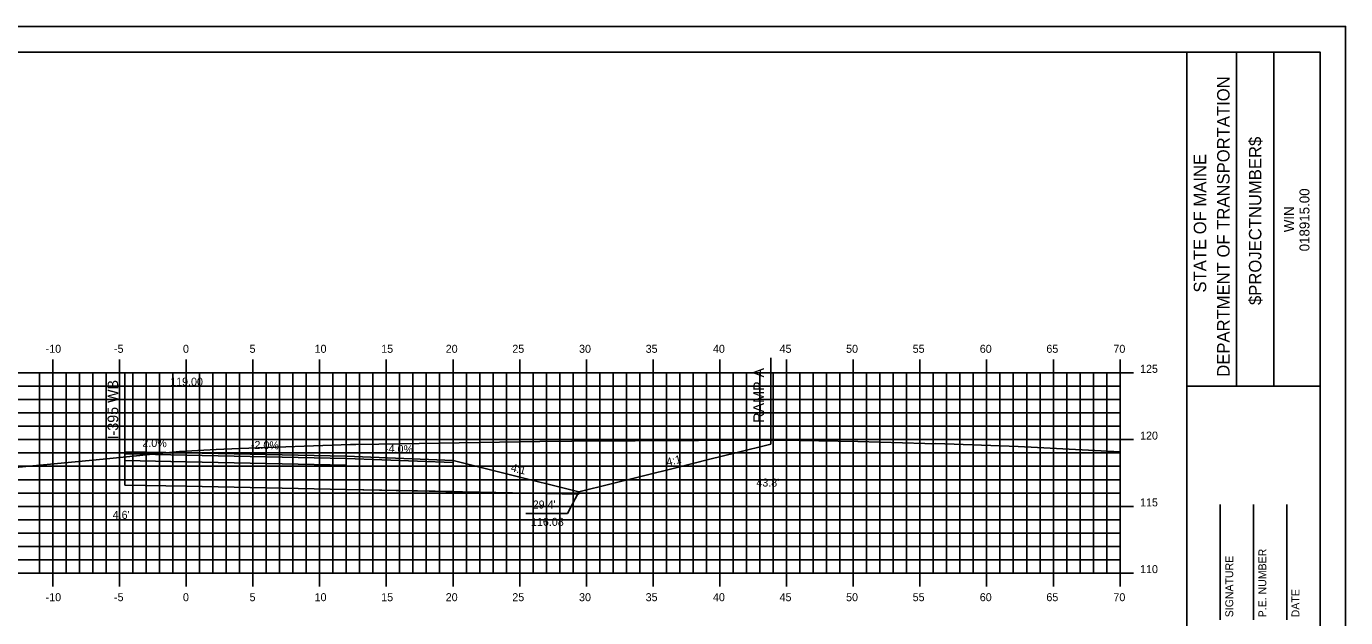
# Model space of a CAD drawing. Extents: x 853291 to 853462, y 365624 to 365734.
# Drawn here: x 853361.8 to 853460.7, y 365689.7 to 365734 of the extents above; entities that cross this region are included whole.
import ezdxf

# ---------------------------------------------------------------- set-up
doc = ezdxf.new("R2010")
doc.units = 0
for name, color, linetype in [('ANNOTATION', 7, 'Continuous'), ('BORDER', 7, 'Continuous'), ('D_Roadway_Centerline', 7, 'Continuous'), ('D_Roadway_Centerline_Text', 7, 'Continuous'), ('D_Roadway_Edge_Shoulder', 7, 'Continuous'), ('D_Roadway_Edge_TW', 7, 'Continuous'), ('D_Roadway_FinishedGrade', 7, 'Continuous'), ('D_Roadway_Pavement', 7, 'Continuous'), ('D_Roadway_SubGrade', 7, 'Continuous'), ('D_Text_Standard', 7, 'Continuous'), ('Default', 7, 'Continuous'), ('H_V ANNOTATION', 7, 'Continuous'), ('M_Roadway_Centerline', 7, 'Continuous'), ('MAJOR', 7, 'Continuous'), ('MINOR', 7, 'Continuous'), ('PLOT BOUNDARY', 7, 'Continuous'), ('S_Roadway_Centerline', 7, 'Continuous')]:
    doc.layers.add(name, color=color, linetype=linetype)

msp = doc.modelspace()

# ---------------------------------------------------------------- linework, layer by layer
at = {"layer": 'ANNOTATION'}
msp.add_lwpolyline([(853399.279, 365697.505), (853402.389, 365697.505), (853403.254, 365699.11)], dxfattribs=at)
at = {"layer": 'BORDER'}
for p, q in [((853448.818, 365627.027), (853448.818, 365732.027)), ((853452.547, 365707.024), (853452.547, 365732.024)), ((853455.342, 365707.024), (853455.342, 365732.024)), ((853448.819, 365707.021), (853458.818, 365707.021)), ((853451.318, 365689.53), (853451.318, 365698.177)), ((853453.818, 365689.53), (853453.818, 365698.177)), ((853456.318, 365689.53), (853456.318, 365698.177))]:
    msp.add_line(p, q, dxfattribs=at)
msp.add_lwpolyline([(853298.818, 365627.027), (853458.818, 365627.027), (853458.818, 365732.027), (853298.818, 365732.027)], close=True, dxfattribs=at)
at = {"layer": 'D_Roadway_Centerline'}
msp.add_line((853393.818, 365699.129), (853393.818, 365699.129), dxfattribs=at)
for points in [[(853403.254, 365699.11), (853410.521, 365700.918), (853413.07, 365701.552), (853415.017, 365702.036), (853417.64, 365702.689)], [(853369.231, 365702.121), (853369.232, 365702.121), (853373.818, 365702.029), (853373.819, 365702.029), (853385.818, 365701.789), (853393.818, 365701.469)], [(853393.818, 365701.469), (853397.818, 365700.469), (853403.254, 365699.11)]]:
    msp.add_lwpolyline(points, dxfattribs=at)
at = {"layer": 'D_Roadway_Edge_Shoulder'}
for points in [[(853373.818, 365702.029), (853369.231, 365702.121), (853369.231, 365701.954), (853373.818, 365701.862)], [(853385.818, 365701.789), (853393.818, 365701.469), (853393.818, 365701.302), (853385.818, 365701.622)]]:
    msp.add_lwpolyline(points, close=True, dxfattribs=at)
at = {"layer": 'D_Roadway_Edge_TW'}
msp.add_lwpolyline([(853373.818, 365702.029), (853385.818, 365701.789), (853385.818, 365701.622), (853373.818, 365701.862)], close=True, dxfattribs=at)
msp.add_lwpolyline([(853385.818, 365701.789), (853385.818, 365701.622)], dxfattribs=at)
at = {"layer": 'D_Roadway_FinishedGrade'}
for p, q in [((853369.231, 365702.121), (853369.231, 365701.871)), ((853369.231, 365702.037), (853369.231, 365701.787)), ((853373.818, 365702.029), (853373.818, 365701.779)), ((853385.818, 365701.789), (853385.818, 365701.539)), ((853393.818, 365701.469), (853393.818, 365701.219))]:
    msp.add_line(p, q, dxfattribs=at)
at = {"layer": 'D_Roadway_Pavement'}
for points in [[(853373.818, 365701.862), (853369.231, 365701.954), (853369.231, 365701.454), (853373.818, 365701.362)], [(853373.818, 365701.862), (853385.818, 365701.622), (853385.818, 365701.122), (853373.818, 365701.362)]]:
    msp.add_lwpolyline(points, close=True, dxfattribs=at)
msp.add_lwpolyline([(853385.818, 365701.622), (853385.818, 365701.122)], dxfattribs=at)
msp.add_lwpolyline([(853385.818, 365701.622), (853385.818, 365701.122)], dxfattribs=at)
at = {"layer": 'D_Roadway_SubGrade'}
for p, q in [((853417.64, 365709.151), (853417.64, 365702.689)), ((853369.231, 365708.025), (853369.231, 365699.621)), ((853385.818, 365699.289), (853403.254, 365698.94)), ((853403.254, 365699.11), (853403.254, 365698.94))]:
    msp.add_line(p, q, dxfattribs=at)
for points in [[(853373.818, 365701.362), (853369.231, 365701.454), (853369.231, 365701.954), (853369.231, 365702.121), (853369.231, 365699.621), (853373.818, 365699.529)], [(853385.818, 365701.122), (853385.818, 365701.622), (853393.818, 365701.302), (853393.818, 365701.469), (853393.818, 365699.129), (853385.818, 365699.289)], [(853373.818, 365701.362), (853385.818, 365701.122), (853385.818, 365699.289), (853373.818, 365699.529)]]:
    msp.add_lwpolyline(points, close=True, dxfattribs=at)
msp.add_lwpolyline([(853385.818, 365701.122), (853385.818, 365699.289)], dxfattribs=at)
at = {"layer": 'Default'}
msp.add_lwpolyline([(853393.818, 365701.469), (853397.818, 365700.469), (853403.254, 365699.11)], dxfattribs=at)
at = {"layer": 'MAJOR'}
for p, q in [((853363.818, 365709.029), (853363.818, 365708.027)), ((853368.818, 365709.029), (853368.818, 365708.027)), ((853373.818, 365709.029), (853373.818, 365708.027)), ((853378.818, 365709.029), (853378.818, 365708.027)), ((853383.818, 365709.029), (853383.818, 365708.027)), ((853388.818, 365709.029), (853388.818, 365708.027)), ((853393.818, 365709.029), (853393.818, 365708.027)), ((853398.818, 365709.029), (853398.818, 365708.027)), ((853403.818, 365709.029), (853403.818, 365708.027)), ((853408.818, 365709.029), (853408.818, 365708.027)), ((853413.818, 365709.029), (853413.818, 365708.027)), ((853418.818, 365709.029), (853418.818, 365708.027)), ((853423.818, 365709.029), (853423.818, 365708.027)), ((853428.818, 365709.029), (853428.818, 365708.027)), ((853433.818, 365709.029), (853433.818, 365708.027)), ((853438.818, 365709.029), (853438.818, 365708.027)), ((853443.818, 365709.029), (853443.818, 365708.027)), ((853303.818, 365708.027), (853443.818, 365708.027)), ((853303.818, 365708.027), (853443.818, 365708.027)), ((853363.818, 365693.027), (853363.818, 365708.027)), ((853368.818, 365693.027), (853368.818, 365708.027)), ((853373.818, 365693.027), (853373.818, 365708.027)), ((853378.818, 365693.027), (853378.818, 365708.027)), ((853383.818, 365693.027), (853383.818, 365708.027)), ((853388.818, 365693.027), (853388.818, 365708.027)), ((853393.818, 365693.027), (853393.818, 365708.027)), ((853398.818, 365693.027), (853398.818, 365708.027)), ((853403.818, 365693.027), (853403.818, 365708.027)), ((853408.818, 365693.027), (853408.818, 365708.027)), ((853413.818, 365693.027), (853413.818, 365708.027)), ((853418.818, 365693.027), (853418.818, 365708.027)), ((853423.818, 365693.027), (853423.818, 365708.027)), ((853428.818, 365693.027), (853428.818, 365708.027)), ((853433.818, 365693.027), (853433.818, 365708.027)), ((853438.818, 365693.027), (853438.818, 365708.027)), ((853444.82, 365708.027), (853442.816, 365708.027)), ((853443.818, 365693.027), (853443.818, 365708.027)), ((853443.818, 365693.027), (853443.818, 365708.027)), ((853303.818, 365703.027), (853443.818, 365703.027)), ((853444.82, 365703.027), (853442.816, 365703.027)), ((853303.818, 365698.027), (853443.818, 365698.027)), ((853444.82, 365698.027), (853442.816, 365698.027)), ((853303.818, 365693.027), (853443.818, 365693.027)), ((853303.818, 365693.027), (853443.818, 365693.027)), ((853363.818, 365692.025), (853363.818, 365693.027)), ((853368.818, 365692.025), (853368.818, 365693.027)), ((853373.818, 365692.025), (853373.818, 365693.027)), ((853378.818, 365692.025), (853378.818, 365693.027)), ((853383.818, 365692.025), (853383.818, 365693.027)), ((853388.818, 365692.025), (853388.818, 365693.027)), ((853393.818, 365692.025), (853393.818, 365693.027)), ((853398.818, 365692.025), (853398.818, 365693.027)), ((853403.818, 365692.025), (853403.818, 365693.027)), ((853408.818, 365692.025), (853408.818, 365693.027)), ((853413.818, 365692.025), (853413.818, 365693.027)), ((853418.818, 365692.025), (853418.818, 365693.027)), ((853423.818, 365692.025), (853423.818, 365693.027)), ((853428.818, 365692.025), (853428.818, 365693.027)), ((853433.818, 365692.025), (853433.818, 365693.027)), ((853438.818, 365692.025), (853438.818, 365693.027)), ((853444.82, 365693.027), (853442.816, 365693.027)), ((853443.818, 365692.025), (853443.818, 365693.027))]:
    msp.add_line(p, q, dxfattribs=at)
at = {"layer": 'MINOR'}
for p, q in [((853362.818, 365693.027), (853362.818, 365708.027)), ((853364.818, 365693.027), (853364.818, 365708.027)), ((853365.818, 365693.027), (853365.818, 365708.027)), ((853366.818, 365693.027), (853366.818, 365708.027)), ((853367.818, 365693.027), (853367.818, 365708.027)), ((853369.818, 365693.027), (853369.818, 365708.027)), ((853370.818, 365693.027), (853370.818, 365708.027)), ((853371.818, 365693.027), (853371.818, 365708.027)), ((853372.818, 365693.027), (853372.818, 365708.027)), ((853374.818, 365693.027), (853374.818, 365708.027)), ((853375.818, 365693.027), (853375.818, 365708.027)), ((853376.818, 365693.027), (853376.818, 365708.027)), ((853377.818, 365693.027), (853377.818, 365708.027)), ((853379.818, 365693.027), (853379.818, 365708.027)), ((853380.818, 365693.027), (853380.818, 365708.027)), ((853381.818, 365693.027), (853381.818, 365708.027)), ((853382.818, 365693.027), (853382.818, 365708.027)), ((853384.818, 365693.027), (853384.818, 365708.027)), ((853385.818, 365693.027), (853385.818, 365708.027)), ((853386.818, 365693.027), (853386.818, 365708.027)), ((853387.818, 365693.027), (853387.818, 365708.027)), ((853389.818, 365693.027), (853389.818, 365708.027)), ((853390.818, 365693.027), (853390.818, 365708.027)), ((853391.818, 365693.027), (853391.818, 365708.027)), ((853392.818, 365693.027), (853392.818, 365708.027)), ((853394.818, 365693.027), (853394.818, 365708.027)), ((853395.818, 365693.027), (853395.818, 365708.027)), ((853396.818, 365693.027), (853396.818, 365708.027)), ((853397.818, 365693.027), (853397.818, 365708.027)), ((853399.818, 365693.027), (853399.818, 365708.027)), ((853400.818, 365693.027), (853400.818, 365708.027)), ((853401.818, 365693.027), (853401.818, 365708.027)), ((853402.818, 365693.027), (853402.818, 365708.027)), ((853404.818, 365693.027), (853404.818, 365708.027)), ((853405.818, 365693.027), (853405.818, 365708.027)), ((853406.818, 365693.027), (853406.818, 365708.027)), ((853407.818, 365693.027), (853407.818, 365708.027)), ((853409.818, 365693.027), (853409.818, 365708.027)), ((853410.818, 365693.027), (853410.818, 365708.027)), ((853411.818, 365693.027), (853411.818, 365708.027)), ((853412.818, 365693.027), (853412.818, 365708.027)), ((853414.818, 365693.027), (853414.818, 365708.027)), ((853415.818, 365693.027), (853415.818, 365708.027)), ((853416.818, 365693.027), (853416.818, 365708.027)), ((853417.818, 365693.027), (853417.818, 365708.027)), ((853419.818, 365693.027), (853419.818, 365708.027)), ((853420.818, 365693.027), (853420.818, 365708.027)), ((853421.818, 365693.027), (853421.818, 365708.027)), ((853422.818, 365693.027), (853422.818, 365708.027)), ((853424.818, 365693.027), (853424.818, 365708.027)), ((853425.818, 365693.027), (853425.818, 365708.027)), ((853426.818, 365693.027), (853426.818, 365708.027)), ((853427.818, 365693.027), (853427.818, 365708.027)), ((853429.818, 365693.027), (853429.818, 365708.027)), ((853430.818, 365693.027), (853430.818, 365708.027)), ((853431.818, 365693.027), (853431.818, 365708.027)), ((853432.818, 365693.027), (853432.818, 365708.027)), ((853434.818, 365693.027), (853434.818, 365708.027)), ((853435.818, 365693.027), (853435.818, 365708.027)), ((853436.818, 365693.027), (853436.818, 365708.027)), ((853437.818, 365693.027), (853437.818, 365708.027)), ((853439.818, 365693.027), (853439.818, 365708.027)), ((853440.818, 365693.027), (853440.818, 365708.027)), ((853441.818, 365693.027), (853441.818, 365708.027)), ((853442.818, 365693.027), (853442.818, 365708.027)), ((853303.818, 365707.027), (853443.818, 365707.027)), ((853443.818, 365707.027), (853442.816, 365707.027)), ((853303.818, 365706.027), (853443.818, 365706.027)), ((853443.818, 365706.027), (853442.816, 365706.027)), ((853303.818, 365705.027), (853443.818, 365705.027)), ((853443.818, 365705.027), (853442.816, 365705.027)), ((853303.818, 365704.027), (853443.818, 365704.027)), ((853443.818, 365704.027), (853442.816, 365704.027)), ((853303.818, 365702.027), (853443.818, 365702.027)), ((853443.818, 365702.027), (853442.816, 365702.027)), ((853303.818, 365701.027), (853443.818, 365701.027)), ((853443.818, 365701.027), (853442.816, 365701.027)), ((853303.818, 365700.027), (853443.818, 365700.027)), ((853443.818, 365700.027), (853442.816, 365700.027)), ((853303.818, 365699.027), (853443.818, 365699.027)), ((853443.818, 365699.027), (853442.816, 365699.027)), ((853303.818, 365697.027), (853443.818, 365697.027)), ((853443.818, 365697.027), (853442.816, 365697.027)), ((853303.818, 365696.027), (853443.818, 365696.027)), ((853443.818, 365696.027), (853442.816, 365696.027)), ((853303.818, 365695.027), (853443.818, 365695.027)), ((853443.818, 365695.027), (853442.816, 365695.027)), ((853303.818, 365694.027), (853443.818, 365694.027)), ((853443.818, 365694.027), (853442.816, 365694.027))]:
    msp.add_line(p, q, dxfattribs=at)
at = {"layer": 'PLOT BOUNDARY'}
msp.add_lwpolyline([(853290.725, 365623.968), (853460.725, 365623.968), (853460.725, 365733.968), (853290.725, 365733.968)], close=True, dxfattribs=at)
at = {"layer": 'S_Roadway_Centerline'}
msp.add_lwpolyline([(853359.138, 365700.764), (853367.599, 365701.559), (853373.32, 365702.129), (853376.075, 365702.281), (853377.802, 365702.359), (853386.143, 365702.671), (853386.523, 365702.657), (853388.262, 365702.69), (853398.792, 365702.864), (853400.32, 365702.888), (853402.714, 365702.906), (853412.215, 365702.965), (853418.283, 365702.975), (853424.168, 365702.885), (853429.18, 365702.741), (853429.699, 365702.715), (853430.02, 365702.74), (853436.178, 365702.513), (853437.619, 365702.439), (853443.818, 365702.121)], dxfattribs=at)

# ---------------------------------------------------------------- texts
at = {"layer": 'ANNOTATION'}
for s, height, rotation, p in [('RAMP A', 0.8, 90, (853417.134, 365704.291)), ('I-395 WB', 0.8, 90, (853368.724, 365703.039)), ('2.0%', 0.6, 358.85103, (853370.529, 365702.495)), ('-2.0%', 0.6, 358.85424, (853378.662, 365702.332)), ('-4.0%', 0.6, 357.70931, (853388.714, 365702.074)), ('4:1', 0.6, 13.97047, (853409.893, 365701.037)), ('4:1', 0.6, 345.96376, (853398.111, 365700.671)), ("29.4' ", 0.6, 360, (853399.791, 365697.868)), ('116.08', 0.6, 360, (853399.663, 365696.568))]:
    msp.add_text(s, height=height, rotation=rotation, dxfattribs=at).set_placement(p)
at = {"layer": 'BORDER'}
for s, height, p in [('DEPARTMENT OF TRANSPORTATION', 0.93176, (853452.025, 365707.733)), ('$PROJECTNUMBER$', 0.93176, (853454.41, 365713.106)), ('STATE OF MAINE', 0.93176, (853450.273, 365714.039)), ('018915.00', 0.7453, (853458.014, 365717.125)), ('WIN', 0.7453, (853456.855, 365718.557)), ('P.E. NUMBER', 0.59055, (853454.779, 365689.722)), ('SIGNATURE', 0.5906, (853452.299, 365689.722)), ('DATE', 0.5906, (853457.259, 365689.722))]:
    msp.add_text(s, height=height, rotation=90, dxfattribs=at).set_placement(p)
at = {"layer": 'D_Roadway_Centerline'}
for s, p in [('C', (853373.813, 365702.029)), ('L', (853373.818, 365702.021))]:
    msp.add_text(s, height=0.0146, dxfattribs=at).set_placement(p)
at = {"layer": 'D_Roadway_Centerline_Text'}
msp.add_text('119.00', height=0.6, dxfattribs=at).set_placement((853372.62, 365707.061))
at = {"layer": 'D_Text_Standard'}
for s, p in [("43.8'", (853416.557, 365699.51)), ("4.6'", (853368.308, 365697.09))]:
    msp.add_text(s, height=0.6, dxfattribs=at).set_placement(p)
at = {"layer": 'H_V ANNOTATION'}
for s, p in [('-10', (853363.283, 365709.527)), ('-5', (853368.409, 365709.527)), ('0', (853373.577, 365709.527)), ('5', (853378.569, 365709.527)), ('10', (853383.443, 365709.527)), ('15', (853388.435, 365709.527)), ('20', (853393.272, 365709.527)), ('25', (853398.264, 365709.527)), ('30', (853403.267, 365709.527)), ('35', (853408.259, 365709.527)), ('40', (853413.304, 365709.527)), ('45', (853418.296, 365709.527)), ('50', (853423.283, 365709.527)), ('55', (853428.275, 365709.527)), ('60', (853433.304, 365709.527)), ('65', (853438.296, 365709.527)), ('70', (853443.32, 365709.527)), ('125', (853445.318, 365708.027)), ('120', (853445.318, 365703.027)), ('115', (853445.318, 365698.027)), ('110', (853445.318, 365693.027)), ('-10', (853363.283, 365690.927)), ('-5', (853368.409, 365690.927)), ('0', (853373.577, 365690.927)), ('5', (853378.569, 365690.927)), ('10', (853383.443, 365690.927)), ('15', (853388.435, 365690.927)), ('20', (853393.272, 365690.927)), ('25', (853398.264, 365690.927)), ('30', (853403.267, 365690.927)), ('35', (853408.259, 365690.927)), ('40', (853413.304, 365690.927)), ('45', (853418.296, 365690.927)), ('50', (853423.283, 365690.927)), ('55', (853428.275, 365690.927)), ('60', (853433.304, 365690.927)), ('65', (853438.296, 365690.927)), ('70', (853443.32, 365690.927))]:
    msp.add_text(s, height=0.6, dxfattribs=at).set_placement(p)
at = {"layer": 'M_Roadway_Centerline'}
for s, p in [('C', (853386.138, 365702.671)), ('L', (853386.143, 365702.663)), ('C', (853430.014, 365702.74)), ('L', (853430.02, 365702.733))]:
    msp.add_text(s, height=0.0146, dxfattribs=at).set_placement(p)

doc.saveas('drawing.dxf')
